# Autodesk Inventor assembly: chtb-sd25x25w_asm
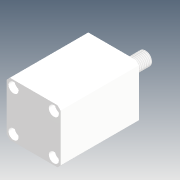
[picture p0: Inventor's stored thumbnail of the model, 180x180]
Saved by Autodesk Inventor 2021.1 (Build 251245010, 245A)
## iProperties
Company: Microsoft
Created: 2018-05
Part Number: chtb-sd25x25w_asm
Description: STEP AP214
Document SubType Name: Assembly
Designer: user
Title: chtb-sd25x25w_asm.STEP
Author: Windows
Revision Number: ÈÎºÎ
Sending System: SolidWorks 2015
Preprocessor: SwSTEP 2.0
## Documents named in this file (4)
- D:\Vault_2016\Projekty\Clamptek\Hydraulic\CHTB\CHTB-25\Inventor\chtb-sd25x25w\chtb-sd25x25w_asm.iam
- D:\Vault_2016\Projekty\Clamptek\Hydraulic\CHTB\CHTB-25\Inventor\chtb-sd25x25w\CHTB-25QG.ipt
- D:\Vault_2016\Projekty\Clamptek\Hydraulic\CHTB\CHTB-25\Inventor\chtb-sd25x25w\CHTB-SD25X25NBT.ipt
- D:\Vault_2016\Projekty\Clamptek\Hydraulic\CHTB\CHTB-25\Inventor\chtb-sd25x25w\CHTB-SD25X25WHSG.ipt
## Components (3 placed, 3 different names)
1. CHTB-25QG_1
2. CHTB-SD25X25NBT_2
3. CHTB-SD25X25WHSG_3
